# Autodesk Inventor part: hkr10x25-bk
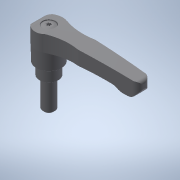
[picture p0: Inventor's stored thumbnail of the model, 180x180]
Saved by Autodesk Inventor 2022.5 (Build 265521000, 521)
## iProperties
Created: 2017-09
Part Number: hkr10x25-bk
Material: 一般
Document SubType Name: Modeling
Designer: imaocorp
Density: 1 g/cm^3
Appearance: 既定
Author: imaocorp
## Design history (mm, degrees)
node "hkr10x25-bk.x_t1"
node "hkr10x25-bk"
node "Base1"
